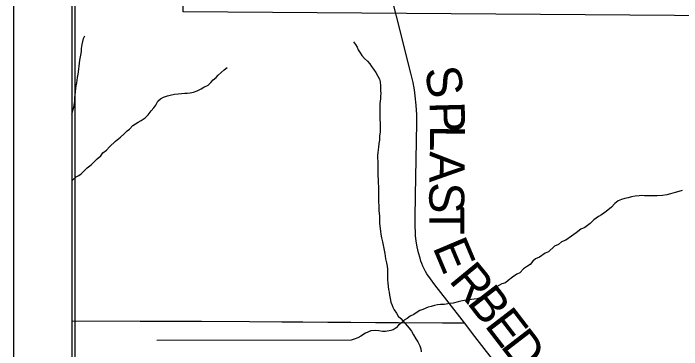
# Model space of a CAD drawing. Extents: x 63.4 to 97.4, y 0.4 to 22.4.
# Drawn here: x 65.412 to 66.497, y 15.037 to 15.582 of the extents above; entities that cross this region are included whole.
import ezdxf

# ---------------------------------------------------------------- set-up
doc = ezdxf.new("R2010")
doc.units = 0
for name, color, linetype in [('GM_X_County_Road', 7, 'Continuous'), ('GM_X_County_Road_Text', 7, 'Continuous'), ('GM_X_Minor_River', 7, 'Continuous'), ('GM_X_Section', 7, 'Continuous'), ('SH_Cut_Line', 7, 'Continuous'), ('SH_Data', 7, 'Continuous')]:
    doc.layers.add(name, color=color, linetype=linetype)

msp = doc.modelspace()

# ---------------------------------------------------------------- linework, layer by layer
at = {"layer": 'GM_X_County_Road'}
for points in [[(65.5072, 16.9001), (65.5072, 14.7073)], [(66.0868, 15.1552), (66.0862, 15.1559), (66.0838, 15.1595), (66.0814, 15.1634), (66.0793, 15.1677), (66.0774, 15.1719), (66.0756, 15.1762), (66.0741, 15.1805), (66.0728, 15.1852), (66.0703, 15.1935), (66.0681, 15.2034), (66.0666, 15.2127), (66.0654, 15.2219), (66.0651, 15.2287), (66.0648, 15.2351), (66.065, 15.25), (66.0654, 15.2873), (66.067, 15.3744), (66.0674, 15.4055), (66.0672, 15.4179), (66.0663, 15.4334), (66.0649, 15.4488), (66.0636, 15.4581), (66.0613, 15.4702), (66.0578, 15.4853), (66.0485, 15.5215), (66.0402, 15.5547), (66.0218, 15.627)], [(66.1446, 15.0801), (66.1162, 15.1172), (66.0968, 15.1416), (66.0894, 15.1516), (66.0868, 15.1552)], [(65.5072, 15.0835), (65.6184, 15.0831), (65.7179, 15.0828), (65.7955, 15.0821), (65.8483, 15.082), (65.8825, 15.082), (65.9229, 15.0813), (65.9601, 15.0812), (66.0005, 15.0809), (66.0378, 15.0806), (66.1092, 15.08), (66.1372, 15.0801), (66.1446, 15.0801)], [(66.2938, 14.8133), (66.2925, 14.8144), (66.2912, 14.8157), (66.2898, 14.8175), (66.2882, 14.8199), (66.2868, 14.8226), (66.2856, 14.8255), (66.2829, 14.8345), (66.2774, 14.8523), (66.2656, 14.8909), (66.2601, 14.9087), (66.255, 14.9234), (66.2505, 14.935), (66.2467, 14.9434), (66.2438, 14.9488), (66.2389, 14.9567), (66.2318, 14.9668), (66.2017, 15.0065), (66.1617, 15.058), (66.1446, 15.0801)]]:
    msp.add_lwpolyline(points, dxfattribs=at)
at = {"layer": 'GM_X_Minor_River'}
for points in [[(65.5106, 15.4304), (65.5117, 15.4361), (65.5121, 15.4406), (65.512, 15.4452), (65.5124, 15.4501), (65.5131, 15.4551), (65.5139, 15.4604), (65.5142, 15.465), (65.5153, 15.4699), (65.5161, 15.4741), (65.5164, 15.4783), (65.5175, 15.4836), (65.5183, 15.4878), (65.5186, 15.4923), (65.5194, 15.4969), (65.5197, 15.5019), (65.5205, 15.5064), (65.5219, 15.5148), (65.5227, 15.5205), (65.523, 15.5254), (65.5241, 15.5319), (65.5249, 15.5368), (65.526, 15.5418), (65.5282, 15.546)], [(65.9645, 15.5362), (65.9676, 15.5321), (65.9703, 15.5275), (65.9722, 15.5233), (65.9752, 15.5184), (65.9779, 15.5143), (65.9825, 15.5093), (65.9871, 15.5048), (65.9913, 15.5003), (65.994, 15.4961), (65.997, 15.4919), (66.0008, 15.4866), (66.0043, 15.4805), (66.007, 15.4756), (66.0081, 15.4711), (66.0082, 15.465), (66.0082, 15.4574), (66.009, 15.4524), (66.0086, 15.4483), (66.0083, 15.4437), (66.0076, 15.4361), (66.0072, 15.4281), (66.0073, 15.4102), (66.0077, 15.4042), (66.0078, 15.3897), (66.0071, 15.3836), (66.0071, 15.3768), (66.006, 15.3711), (66.0053, 15.3654), (66.0049, 15.3608), (66.0042, 15.3566), (66.0038, 15.3517), (66.0039, 15.3376), (66.0043, 15.3319), (66.0043, 15.3251), (66.004, 15.3186), (66.0044, 15.3129), (66.0048, 15.3087), (66.0052, 15.3), (66.0053, 15.2913), (66.0053, 15.2776), (66.0058, 15.2692), (66.0058, 15.2624), (66.0066, 15.2533), (66.0066, 15.2476), (66.007, 15.2419), (66.0074, 15.2373), (66.0078, 15.2331), (66.0082, 15.2282), (66.009, 15.224), (66.0102, 15.2183), (66.0117, 15.2115), (66.0133, 15.2035), (66.0145, 15.1982), (66.0153, 15.1929), (66.0168, 15.1841), (66.018, 15.1777), (66.0192, 15.172), (66.0196, 15.1674), (66.0197, 15.1496), (66.0201, 15.145), (66.0208, 15.1393), (66.0216, 15.1344), (66.0224, 15.1298), (66.0232, 15.1249), (66.024, 15.1196), (66.0251, 15.1139), (66.0267, 15.1097), (66.0286, 15.1055), (66.0309, 15.1013), (66.0344, 15.0957), (66.0374, 15.0911), (66.0416, 15.0873), (66.055, 15.0714), (66.0588, 15.0665), (66.0622, 15.0608), (66.0661, 15.0544), (66.0691, 15.0491), (66.0722, 15.0426), (66.0738, 15.0381), (66.0745, 15.0331)], [(65.5072, 15.3108), (65.5089, 15.3125), (65.5142, 15.3171), (65.5184, 15.3194), (65.5225, 15.3221), (65.5275, 15.327), (65.5324, 15.3316), (65.5384, 15.3366), (65.5437, 15.3416), (65.5482, 15.3465), (65.5543, 15.3511), (65.5577, 15.3561), (65.5634, 15.3603), (65.5683, 15.3656), (65.5781, 15.3748), (65.5864, 15.3813), (65.5917, 15.3863), (65.597, 15.392), (65.6011, 15.3943), (65.6061, 15.4004), (65.6151, 15.4061), (65.6201, 15.4084), (65.6265, 15.413), (65.6314, 15.418), (65.6363, 15.4241), (65.6405, 15.4291), (65.6438, 15.4336), (65.6469, 15.4397), (65.651, 15.4439), (65.6563, 15.4462), (65.6628, 15.4485), (65.6669, 15.4497), (65.6738, 15.4513), (65.6798, 15.452), (65.6905, 15.4529), (65.6946, 15.4529), (65.6996, 15.4533), (65.7049, 15.4544), (65.7109, 15.4568), (65.717, 15.4602), (65.7215, 15.4629), (65.7284, 15.466), (65.7329, 15.4702), (65.737, 15.4747), (65.7416, 15.4782), (65.745, 15.4824), (65.7495, 15.4866), (65.7544, 15.4908), (65.7593, 15.4946)], [(65.5072, 15.4178), (65.5076, 15.4189), (65.5084, 15.4231), (65.5106, 15.4304)], [(66.4984, 15.2951), (66.4927, 15.2935), (66.4867, 15.2916), (66.4795, 15.2893), (66.4734, 15.2881), (66.4666, 15.2866), (66.4578, 15.2862), (66.4491, 15.2861), (66.4423, 15.2865), (66.4373, 15.2864), (66.4328, 15.2868), (66.4286, 15.2864), (66.4222, 15.286), (66.4161, 15.2844), (66.4108, 15.2833), (66.4051, 15.2817), (66.3998, 15.2802), (66.3945, 15.2779), (66.3892, 15.2737), (66.3835, 15.2679), (66.3748, 15.2611), (66.3673, 15.2553), (66.3623, 15.253), (66.3548, 15.2473), (66.3491, 15.2412), (66.3404, 15.2351), (66.334, 15.2324), (66.326, 15.2262), (66.3188, 15.2209), (66.3094, 15.2144), (66.3022, 15.2117), (66.2976, 15.2075), (66.2912, 15.2048), (66.281, 15.1956), (66.2757, 15.1933), (66.2666, 15.1868), (66.2602, 15.1841), (66.2556, 15.1803), (66.2515, 15.1746), (66.247, 15.1723), (66.2409, 15.1677), (66.2349, 15.1612), (66.2296, 15.1593), (66.2227, 15.1543), (66.2156, 15.149), (66.2114, 15.1451), (66.2057, 15.1432), (66.1966, 15.1386), (66.1891, 15.1336), (66.1826, 15.129), (66.1762, 15.1241), (66.1713, 15.121), (66.1652, 15.1191), (66.1603, 15.1183), (66.1519, 15.1175), (66.1474, 15.1167), (66.139, 15.1151), (66.1345, 15.1144), (66.1265, 15.112), (66.1208, 15.1113), (66.1117, 15.1101), (66.106, 15.1097), (66.1011, 15.1093), (66.0962, 15.1081), (66.0909, 15.1066), (66.0859, 15.1054), (66.0772, 15.1019), (66.0723, 15.1004), (66.0678, 15.0973), (66.0628, 15.0939), (66.0568, 15.0908), (66.0519, 15.087), (66.0469, 15.0843), (66.0424, 15.0801), (66.0379, 15.0763), (66.0341, 15.0721), (66.0292, 15.069), (66.025, 15.0679), (66.0167, 15.0659), (66.0117, 15.0659), (66.0056, 15.067), (65.9999, 15.0677), (65.9927, 15.0673), (65.984, 15.0631)], [(65.984, 15.0631), (65.9765, 15.0585), (65.9719, 15.0558), (65.9658, 15.0535), (65.9609, 15.052)], [(65.9609, 15.052), (65.645, 15.0513)]]:
    msp.add_lwpolyline(points, dxfattribs=at)
at = {"layer": 'GM_X_Section'}
msp.add_lwpolyline([(66.6878, 16.5693), (66.716, 16.5687), (66.7072, 15.5775), (66.7036, 15.5772), (65.6882, 15.5852), (65.6938, 16.5825)], close=True, dxfattribs=at)
at = {"layer": 'SH_Cut_Line'}
msp.add_lwpolyline([(65.5072, 16.9001), (65.5072, 14.7073)], dxfattribs=at)
at = {"layer": 'SH_Data'}
for p, q in [((65.4123, 21.4197), (65.4123, 14.4197)), ((65.5123, 21.3197), (65.5123, 14.5197))]:
    msp.add_line(p, q, dxfattribs=at)

# ---------------------------------------------------------------- texts
at = {"layer": 'GM_X_County_Road_Text'}
for s, rotation, p in [('S', 280.2271, (66.0799, 15.4917)), ('P', 271.4731, (66.0882, 15.4389)), ('L', 269.2886, (66.0892, 15.4011)), ('A', 269.2277, (66.0886, 15.3587)), ('S', 269.2493, (66.088, 15.3086)), ('T', 270.2559, (66.0875, 15.2692)), ('E', 292.8504, (66.0925, 15.2029)), ('R', 309.484, (66.1183, 15.1484)), ('B', 307.6162, (66.1477, 15.1127)), ('E', 307.6187, (66.1762, 15.0758)), ('D', 307.5919, (66.2021, 15.0421))]:
    msp.add_text(s, height=0.0568, rotation=rotation, dxfattribs=at).set_placement(p)

doc.saveas('drawing.dxf')
